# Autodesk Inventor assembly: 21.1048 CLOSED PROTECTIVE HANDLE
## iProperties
Created: 2007-02
Part Number: 21.1048 CLOSED PROTECTIVE HANDLE
Document SubType Name: Assembly
Designer: Andy Moles
Author: Andy Moles
